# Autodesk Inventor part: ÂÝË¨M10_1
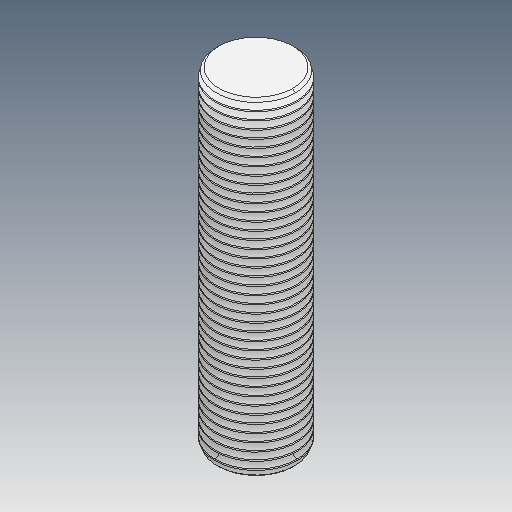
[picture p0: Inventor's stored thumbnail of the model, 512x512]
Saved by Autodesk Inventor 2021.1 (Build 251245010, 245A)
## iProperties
Created: 2021-05
Part Number: ÂÝË¨M10_1
Material: Ogólny
Document SubType Name: Modeling
Designer: user
Density: 1 g/cm^3
Appearance: Domyślna
Author: user
Revision Number: ÈÎºÎ
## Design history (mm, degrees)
feature "ÊäÈë1"
node "Bryła1"
